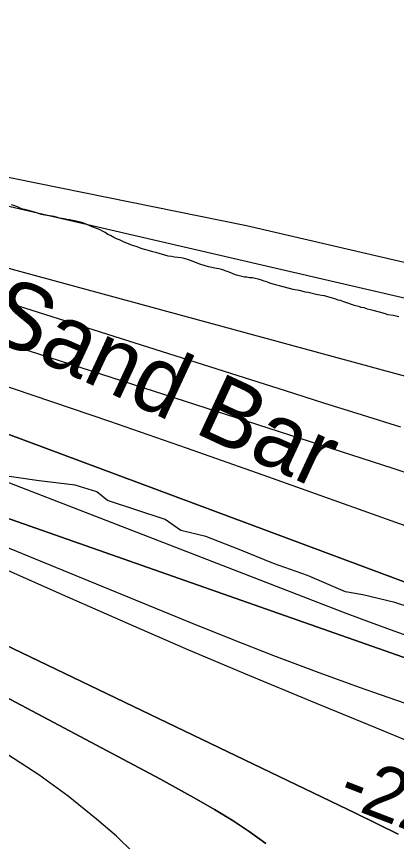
# Model space of a CAD drawing. Extents: x 3263578 to 3301413, y 764927 to 798602.
# Drawn here: x 3282869 to 3283343, y 784025 to 785055 of the extents above; entities that cross this region are included whole.
import ezdxf

# ---------------------------------------------------------------- set-up
doc = ezdxf.new("R2010")
doc.units = 0
for name, color, linetype in [('V-RIVR-EDGE', 7, 'Continuous'), ('V-RIVR-IDEN', 7, 'Continuous'), ('V-RIVR-RANG', 7, 'Continuous'), ('V-SITE-VEGE', 7, 'Continuous'), ('V-TOPO-DPTH', 7, 'Continuous'), ('V-TOPO-MAJR', 7, 'Continuous'), ('V-TOPO-MINR', 7, 'Continuous'), ('V-TOPO-WATR', 7, 'Continuous')]:
    doc.layers.add(name, color=color, linetype=linetype)

msp = doc.modelspace()

# ---------------------------------------------------------------- linework, layer by layer
at = {"layer": 'V-RIVR-EDGE'}
msp.add_lwpolyline([(3283395.5, 784305.8), (3283340.7, 784323.4), (3283300.8, 784333), (3283279, 784337), (3283231.7, 784357.1), (3283189.2, 784372.4), (3283146.2, 784389.5), (3283104.9, 784405.7), (3283073.6, 784413.6), (3283054.1, 784427.1), (3282982, 784450.7), (3282969, 784461.6), (3282941.6, 784470), (3282896.9, 784475.3), (3282833.4, 784484.6)], dxfattribs=at)
at = {"layer": 'V-SITE-VEGE'}
for points in [[(3283085.7, 784750.2), (3283081.9, 784751.7), (3283077.9, 784752.8), (3283073.9, 784753.5), (3283065.6, 784754.5), (3283061.8, 784755.2), (3283057.6, 784755.7), (3283042.2, 784760.4), (3283038.7, 784761.1), (3283034.7, 784762.2), (3283031.5, 784763.3), (3283028.3, 784764.1), (3283024.3, 784765.5), (3283021.3, 784766.7), (3283017.9, 784768), (3283013.3, 784769.2), (3283001.9, 784773.7), (3282996.9, 784776), (3282993.4, 784777.5), (3282990.2, 784779), (3282985.8, 784781.4), (3282982.6, 784782.8), (3282979, 784785.2), (3282975.8, 784787.1), (3282973.1, 784788.5), (3282963.1, 784792.4), (3282953.5, 784796.5), (3282950.1, 784797.8), (3282943.1, 784799.4), (3282934.6, 784801), (3282931.2, 784801.5), (3282928.2, 784802.4), (3282922.4, 784803.3), (3282918.6, 784804.4), (3282915.4, 784805.1), (3282903.9, 784807), (3282899.7, 784807.9), (3282892.1, 784810.1), (3282888.1, 784811.4), (3282881.7, 784813.2), (3282878.5, 784813.9), (3282874.9, 784815), (3282869.9, 784817.1), (3282862.5, 784820)], [(3283345.4, 784680.1), (3283342.2, 784680.8), (3283339, 784681.7), (3283331.9, 784682.7), (3283328.9, 784683.6), (3283321.5, 784686), (3283313.7, 784688), (3283310.1, 784688.7), (3283306.3, 784689.8), (3283302.3, 784691.1), (3283298.7, 784691.8), (3283295.7, 784692.9), (3283291.9, 784693.6), (3283288.9, 784694.5), (3283280.7, 784697.7), (3283277.1, 784698.8), (3283272.9, 784700.3), (3283269.9, 784701), (3283266.9, 784701.9), (3283263.9, 784703), (3283257.1, 784705.1), (3283252.6, 784706.1), (3283249.2, 784706.5), (3283242.6, 784707.7), (3283232.6, 784710.4), (3283229.1, 784710.9), (3283221.5, 784712.9), (3283218.5, 784713.4), (3283213.9, 784714.3), (3283196.5, 784718.6), (3283191.6, 784719.9), (3283184.8, 784722.1), (3283180.8, 784723.6), (3283177.4, 784724.5), (3283174.4, 784725.6), (3283170.2, 784726.9), (3283166.2, 784728), (3283163, 784728.5), (3283159.2, 784728.8), (3283155.8, 784729.5), (3283152.8, 784729.7), (3283149.5, 784730.2), (3283143.1, 784732), (3283139.5, 784733.3), (3283135.9, 784735), (3283132.5, 784736.3), (3283124.3, 784738.9), (3283121.1, 784739.8), (3283118.1, 784740.3), (3283107.9, 784742.6), (3283104.1, 784743.7), (3283097.3, 784745.9), (3283085.7, 784750.2)]]:
    msp.add_lwpolyline(points, dxfattribs=at)
at = {"layer": 'V-TOPO-DPTH'}
for p, q in [((3283338.4, 784490.7), (3282640.5, 784715.8)), ((3283359.8, 784483.7), (3283338.4, 784490.7))]:
    msp.add_line(p, q, dxfattribs=at)
for points in [[(3281959.7, 784892.1), (3281987.8, 784859.4), (3282016.9, 784827.6), (3282047.6, 784797.3), (3282079.2, 784768), (3282081.7, 784765.8), (3282115.6, 784736.5), (3282150, 784707.7), (3282184.9, 784679.6), (3282220.2, 784652), (3282489, 784446.1), (3283292.2, 784060.3), (3283318.6, 784047.5), (3283344.8, 784034.4)], [(3281959.7, 784892.1), (3281987.8, 784859.4), (3282016.9, 784827.6), (3282047.6, 784797.3), (3282079.2, 784768), (3282081.7, 784765.8), (3282115.6, 784736.5), (3282150, 784707.7), (3282184.9, 784679.6), (3282220.2, 784652), (3282489, 784446.1), (3283292.2, 784060.3), (3283318.6, 784047.5), (3283344.8, 784034.4)], [(3283179.7, 784022.8), (3283158.9, 784037.8), (3283137.5, 784051.9), (3283115.5, 784065.2), (3283093.3, 784078.2), (3283070.8, 784090.7), (3283048.2, 784103), (3282506.9, 784390.4), (3282488.9, 784400.1), (3282471, 784410), (3282453.3, 784420.3), (3282435.7, 784430.7), (3282259.4, 784537.1), (3282225.3, 784558.8), (3282191.9, 784581.4), (3282159.5, 784605.6), (3282127.8, 784630.7), (3282096.9, 784656.7), (3282066.1, 784683), (3282035.7, 784709.6), (3282005.5, 784736.5), (3281998.8, 784742.6), (3281965.4, 784772.8)], [(3281965.4, 784772.8), (3281998.8, 784742.6), (3282005.5, 784736.5), (3282035.7, 784709.6), (3282066.1, 784683), (3282096.9, 784656.7), (3282127.8, 784630.7), (3282159.5, 784605.6), (3282191.9, 784581.4), (3282225.3, 784558.8), (3282259.4, 784537.1), (3282435.7, 784430.7), (3282453.3, 784420.3), (3282471, 784410), (3282488.9, 784400.1), (3282506.9, 784390.4), (3283048.2, 784103), (3283070.8, 784090.7), (3283093.3, 784078.2), (3283115.5, 784065.2), (3283137.5, 784051.9), (3283158.9, 784037.8), (3283179.7, 784022.8)], [(3282670.2, 784603.3), (3283436.9, 784317.6)], [(3282670.2, 784603.3), (3283436.9, 784317.6)], [(3283356.1, 784150.8), (3283323.9, 784164.1), (3283235.8, 784200.3), (3283159.7, 784232), (3283083.7, 784264.2), (3283008.1, 784296.9), (3282932.6, 784330.1), (3282543.4, 784502.9)], [(3283356.1, 784150.8), (3283323.9, 784164.1), (3283235.8, 784200.3), (3283159.7, 784232), (3283083.7, 784264.2), (3283008.1, 784296.9), (3282932.6, 784330.1), (3282543.4, 784502.9)], [(3282737, 784470.8), (3283390.2, 784241.8)], [(3283390.2, 784241.8), (3282737, 784470.8)]]:
    msp.add_lwpolyline(points, dxfattribs=at)
at = {"layer": 'V-TOPO-MAJR'}
for points in [[(3280955.5, 789209.2), (3281961, 788391.5), (3282471.7, 787832.1), (3282972.1, 787293.3), (3283564.2, 786549.4), (3284187.3, 785938.5), (3284963.7, 785173.7), (3285326.4, 784855.4), (3285444, 784768), (3285725.2, 784613.8), (3285781.4, 784557.3), (3285781.2, 784480.5), (3285755.4, 784408.9), (3285719.5, 784373.1), (3285678.4, 784342.5), (3285606.7, 784332.4), (3284526.7, 784458), (3283539, 784660.1), (3282689.6, 784856.8), (3282306.2, 785103.5), (3281841.1, 785457.9)], [(3283607.3, 783140.4), (3283032, 783990.3), (3283013.7, 784011.9), (3282993.3, 784032), (3282968.3, 784053.3), (3282933, 784081.7), (3282896.6, 784108.6), (3282858.7, 784133.2), (3282819.7, 784156.4), (3282535.8, 784313.8), (3282521.1, 784321.9), (3282506.3, 784330.1), (3282491.5, 784338.1), (3282476.7, 784346.2), (3282462, 784354.4), (3282447.4, 784362.7), (3282432.9, 784371.4), (3282418.6, 784380.2), (3281985.6, 784652.4), (3281939.5, 784683.5)]]:
    msp.add_lwpolyline(points, dxfattribs=at)
at = {"layer": 'V-TOPO-MINR'}
for p, q in [((3283204.1, 784587.6), (3282656.8, 784761)), ((3283338.4, 784490.7), (3282640.5, 784715.8)), ((3283252.1, 784572.4), (3283204.1, 784587.6)), ((3283300.1, 784557.3), (3283252.1, 784572.4)), ((3283348.1, 784542.2), (3283300.1, 784557.3)), ((3283359.8, 784483.7), (3283338.4, 784490.7))]:
    msp.add_line(p, q, dxfattribs=at)
for points in [[(3280773.6, 787080.7), (3280825.2, 786788.5), (3280989.8, 786138.8), (3281113.7, 785969.3), (3281498.4, 785695.6), (3281772.4, 785433.2), (3281863.9, 785380), (3282654.8, 784795.9), (3284438.9, 784310.8), (3284897.9, 784262.5), (3285627.4, 784239.2), (3285928, 784290), (3286001.1, 784358.4), (3286031.3, 784422.7), (3286040, 784465.6), (3286031.5, 784508.6), (3286001.5, 784534.4), (3285915.8, 784577.5), (3285714.3, 784642.4), (3285422.9, 784814.8), (3284904.7, 785270.9), (3284121.3, 786032.5), (3283569.1, 786587.4), (3283000.1, 787318.4)], [(3280798.8, 787096.9), (3281454.2, 786344.7), (3282082.5, 785744.1), (3282128.4, 785662), (3282265.9, 785390.3), (3282485.4, 785092.8), (3282633.5, 784938.8), (3282720.4, 784882.3), (3283155.4, 784794.2), (3283488, 784716.6)], [(3283344.8, 784034.4), (3283318.6, 784047.5), (3283292.2, 784060.3), (3282489, 784446.1), (3282220.2, 784652), (3282184.9, 784679.6), (3282150, 784707.7), (3282115.6, 784736.5), (3282081.7, 784765.8), (3282079.2, 784768), (3282047.6, 784797.3), (3282016.9, 784827.6), (3281987.8, 784859.4), (3281959.7, 784892.1)], [(3283179.7, 784022.8), (3283158.9, 784037.8), (3283137.5, 784051.9), (3283115.5, 784065.2), (3283093.3, 784078.2), (3283070.8, 784090.7), (3283048.2, 784103), (3282506.9, 784390.4), (3282488.9, 784400.1), (3282471, 784410), (3282453.3, 784420.3), (3282435.7, 784430.7), (3282259.4, 784537.1), (3282225.3, 784558.8), (3282191.9, 784581.4), (3282159.5, 784605.6), (3282127.8, 784630.7), (3282096.9, 784656.7), (3282066.1, 784683), (3282035.7, 784709.6), (3282005.5, 784736.5), (3281998.8, 784742.6), (3281965.4, 784772.8)], [(3283449, 784385), (3283176.2, 784482.3), (3283080.7, 784516), (3282985.1, 784549.3), (3282889.3, 784582), (3282793.3, 784614.3)], [(3283369, 784277.2), (3283339.6, 784287.7), (3283310.3, 784298.4), (3283281.1, 784309.4), (3283252, 784320.5), (3282562.6, 784587.8)], [(3283363.2, 784194.1), (3283322.7, 784208.2), (3283296.4, 784217.6), (3283242.9, 784237), (3283189.6, 784256.9), (3283136.7, 784277.6), (3283083.9, 784298.8), (3282535.8, 784523.6)], [(3283356.1, 784150.8), (3283323.9, 784164.1), (3283235.8, 784200.3), (3283159.7, 784232), (3283083.7, 784264.2), (3283008.1, 784296.9), (3282932.6, 784330.1), (3282543.4, 784502.9)], [(3283390.2, 784241.8), (3282737, 784470.8)]]:
    msp.add_lwpolyline(points, dxfattribs=at)
at = {"layer": 'V-TOPO-WATR'}
msp.add_lwpolyline([(3283436.9, 784317.6), (3282670.2, 784603.3)], dxfattribs=at)

# ---------------------------------------------------------------- texts
at = {"layer": 'V-RIVR-IDEN'}
msp.add_text('Sand Bar', height=83, rotation=335.0627, dxfattribs=at).set_placement((3282825.3, 784658.7))
at = {"layer": 'V-RIVR-RANG'}
msp.add_text('-22', height=67, rotation=338.9253, dxfattribs=at).set_placement((3283266.8, 784073.8))

doc.saveas('drawing.dxf')
